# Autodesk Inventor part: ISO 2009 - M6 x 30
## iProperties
Comments: To add or edit properties for Autodesk Inventor files, use iProperties.
Created: 2005-06
Part Number: ISO 2009 - M6 x 30
Vendor: Autodesk Inc.
Document SubType Name: Modeling
Designer: John Blackburn
Material: Default
Description: Countersunk Screw
Standard: ISO 2009
Alert: To add or edit properties for Autodesk Inventor files, use iProperties.
Control State: 0
Master: False
Checked Out: False
Shininess: 64.0
Length Units: 11269
Angle Units: 11279
Time Units: 11290
Mass Units: 11283
Length Display Precision: 3
Angle Display Precision: 2
Compacted: True
EGR: 1
Density: 0.0
Volumn: 0.0
Area: 0.0
PropertySet Name: Model Information
Author: John Blackburn
Revision Number: 8
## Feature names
1. Body [Revolution]
2. Slot [Extrusion]
3. Chamfer1
